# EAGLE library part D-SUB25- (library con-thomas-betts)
D-Subminiatur Connector Source: Electronioc Interconnects European Edition 1998
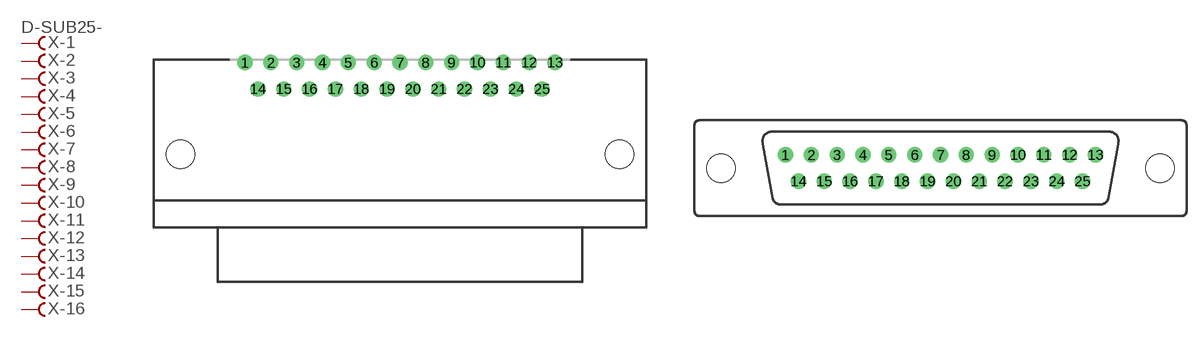
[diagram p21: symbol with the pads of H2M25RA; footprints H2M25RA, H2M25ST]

Designator prefix X; gates -1=FV -2=F -3=F -4=F -5=F -6=F -7=F -8=F -9=F -10=F -11=F -12=F -13=F -14=F -15=F -16=F -17=F -18=F -19=F -20=F -21=F -22=F -23=F -24=F -25=F

## D-SUB25-H2M25RA (OC_FARNELL: unknown; OC_NEWARK: unknown)  [H2M25RA]
1  -1:F  pas
2  -2:F  pas
3  -3:F  pas
4  -4:F  pas
5  -5:F  pas
6  -6:F  pas
7  -7:F  pas
8  -8:F  pas
9  -9:F  pas
10  -10:F  pas
11  -11:F  pas
12  -12:F  pas
13  -13:F  pas
14  -14:F  pas
15  -15:F  pas
16  -16:F  pas
17  -17:F  pas
18  -18:F  pas
19  -19:F  pas
20  -20:F  pas
21  -21:F  pas
22  -22:F  pas
23  -23:F  pas
24  -24:F  pas
25  -25:F  pas

## D-SUB25-H2M25ST (OC_FARNELL: unknown; OC_NEWARK: unknown)  [H2M25ST]
Pads as for H2M25RA

## D-SUB25-H2R25RA (OC_FARNELL: unknown; OC_NEWARK: unknown)  [H2R25RA]
Pads as for H2M25RA

## D-SUB25-H2R25ST (MF: TYCO ELECTRONICS; MPN: H2R25ST29J; OC_FARNELL: unknown; OC_NEWARK: 16F4224)  [H2R25ST]
Pads as for H2M25RA

## D-SUB25-H3M25RA (OC_FARNELL: unknown; OC_NEWARK: unknown)  [H3M25RA]
Pads as for H2M25RA

## D-SUB25-H5M25RA (MPN: H5M25RA29CS; OC_FARNELL: unknown; OC_NEWARK: 93F8324)  [H5M25RA]
Pads as for H2M25RA

## D-SUB25-H5R25RA (MPN: H5R25RA29CS; OC_FARNELL: unknown; OC_NEWARK: 93F8340)  [H5R25RA]
Pads as for H2M25RA

## Footprint H2M25RA (pad centres in mm)
THOMAS&BETTS H2M25RA29A
drill 1.092 round: 1 -16.612,7.925; 2 -13.843,7.925; 3 -11.074,7.925; 4 -8.306,7.925; 5 -5.537,7.925; 6 -2.769,7.925; 7 0,7.925; 8 2.769,7.925; 9 5.537,7.925; 10 8.306,7.925; 11 11.074,7.925; 12 13.843,7.925; 13 16.612,7.925; 14 -15.227,5.08; 15 -12.459,5.08; 16 -9.69,5.08; 17 -6.921,5.08; 18 -4.153,5.08; 19 -1.384,5.08; 20 1.384,5.08; 21 4.153,5.08; 22 6.921,5.08; 23 9.69,5.08; 24 12.459,5.08; 25 15.227,5.08
hole 3.048 at -23.52,-1.905
hole 3.048 at 23.52,-1.905

## Footprint H2M25ST (pad centres in mm)
THOMAS&BETTS H2M25ST29x
drill 1.092 round: 1 -16.612,1.422; 2 -13.843,1.422; 3 -11.074,1.422; 4 -8.306,1.422; 5 -5.537,1.422; 6 -2.769,1.422; 7 0,1.422; 8 2.769,1.422; 9 5.537,1.422; 10 8.306,1.422; 11 11.074,1.422; 12 13.843,1.422; 13 16.612,1.422; 14 -15.227,-1.422; 15 -12.459,-1.422; 16 -9.69,-1.422; 17 -6.921,-1.422; 18 -4.153,-1.422; 19 -1.384,-1.422; 20 1.384,-1.422; 21 4.153,-1.422; 22 6.921,-1.422; 23 9.69,-1.422; 24 12.459,-1.422; 25 15.227,-1.422
hole 3.048 at -23.52,0
hole 3.048 at 23.52,0

## Footprint H2R25RA (pad centres in mm)
THOMAS&BETTS H2R25RA29A
drill 1.092 round: 1 16.612,7.925; 2 13.843,7.925; 3 11.074,7.925; 4 8.306,7.925; 5 5.537,7.925; 6 2.769,7.925; 7 0,7.925; 8 -2.769,7.925; 9 -5.537,7.925; 10 -8.306,7.925; 11 -11.074,7.925; 12 -13.843,7.925; 13 -16.612,7.925; 14 15.227,5.08; 15 12.459,5.08; 16 9.69,5.08; 17 6.921,5.08; 18 4.153,5.08; 19 1.384,5.08; 20 -1.384,5.08; 21 -4.153,5.08; 22 -6.921,5.08; 23 -9.69,5.08; 24 -12.459,5.08; 25 -15.227,5.08
hole 3.048 at -23.52,-1.905
hole 3.048 at 23.52,-1.905

## Footprint H2R25ST (pad centres in mm)
THOMAS&BETTS H2R25ST29x
drill 1.092 round: 1 16.612,1.422; 2 13.843,1.422; 3 11.074,1.422; 4 8.306,1.422; 5 5.537,1.422; 6 2.769,1.422; 7 0,1.422; 8 -2.769,1.422; 9 -5.537,1.422; 10 -8.306,1.422; 11 -11.074,1.422; 12 -13.843,1.422; 13 -16.612,1.422; 14 15.227,-1.422; 15 12.459,-1.422; 16 9.69,-1.422; 17 6.921,-1.422; 18 4.153,-1.422; 19 1.384,-1.422; 20 -1.384,-1.422; 21 -4.153,-1.422; 22 -6.921,-1.422; 23 -9.69,-1.422; 24 -12.459,-1.422; 25 -15.227,-1.422
hole 3.048 at -23.52,0
hole 3.048 at 23.52,0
